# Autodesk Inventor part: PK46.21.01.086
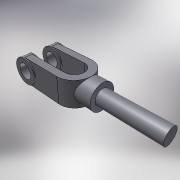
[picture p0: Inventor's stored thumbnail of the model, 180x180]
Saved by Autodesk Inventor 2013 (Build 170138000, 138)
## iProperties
Created: 2005-03
Part Number: PK46.21.01.086
Material: Steel, Mild
Document SubType Name: Modeling
Designer: salex
Manufacturer: Standard
Standards Organization: Custom
Density: 7.86 g/cm^3
Mass: 167.426 g
Surface Area: 89.3279 cm^2
Volume: 21.301 cm^3
Author: salex
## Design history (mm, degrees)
feature "Sculpt1"
body "Solid2"
feature "Surface1"
body "Srf1"
